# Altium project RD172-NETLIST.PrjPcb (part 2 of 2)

## Sheet 7.SchDoc
size 420 x 297 mm
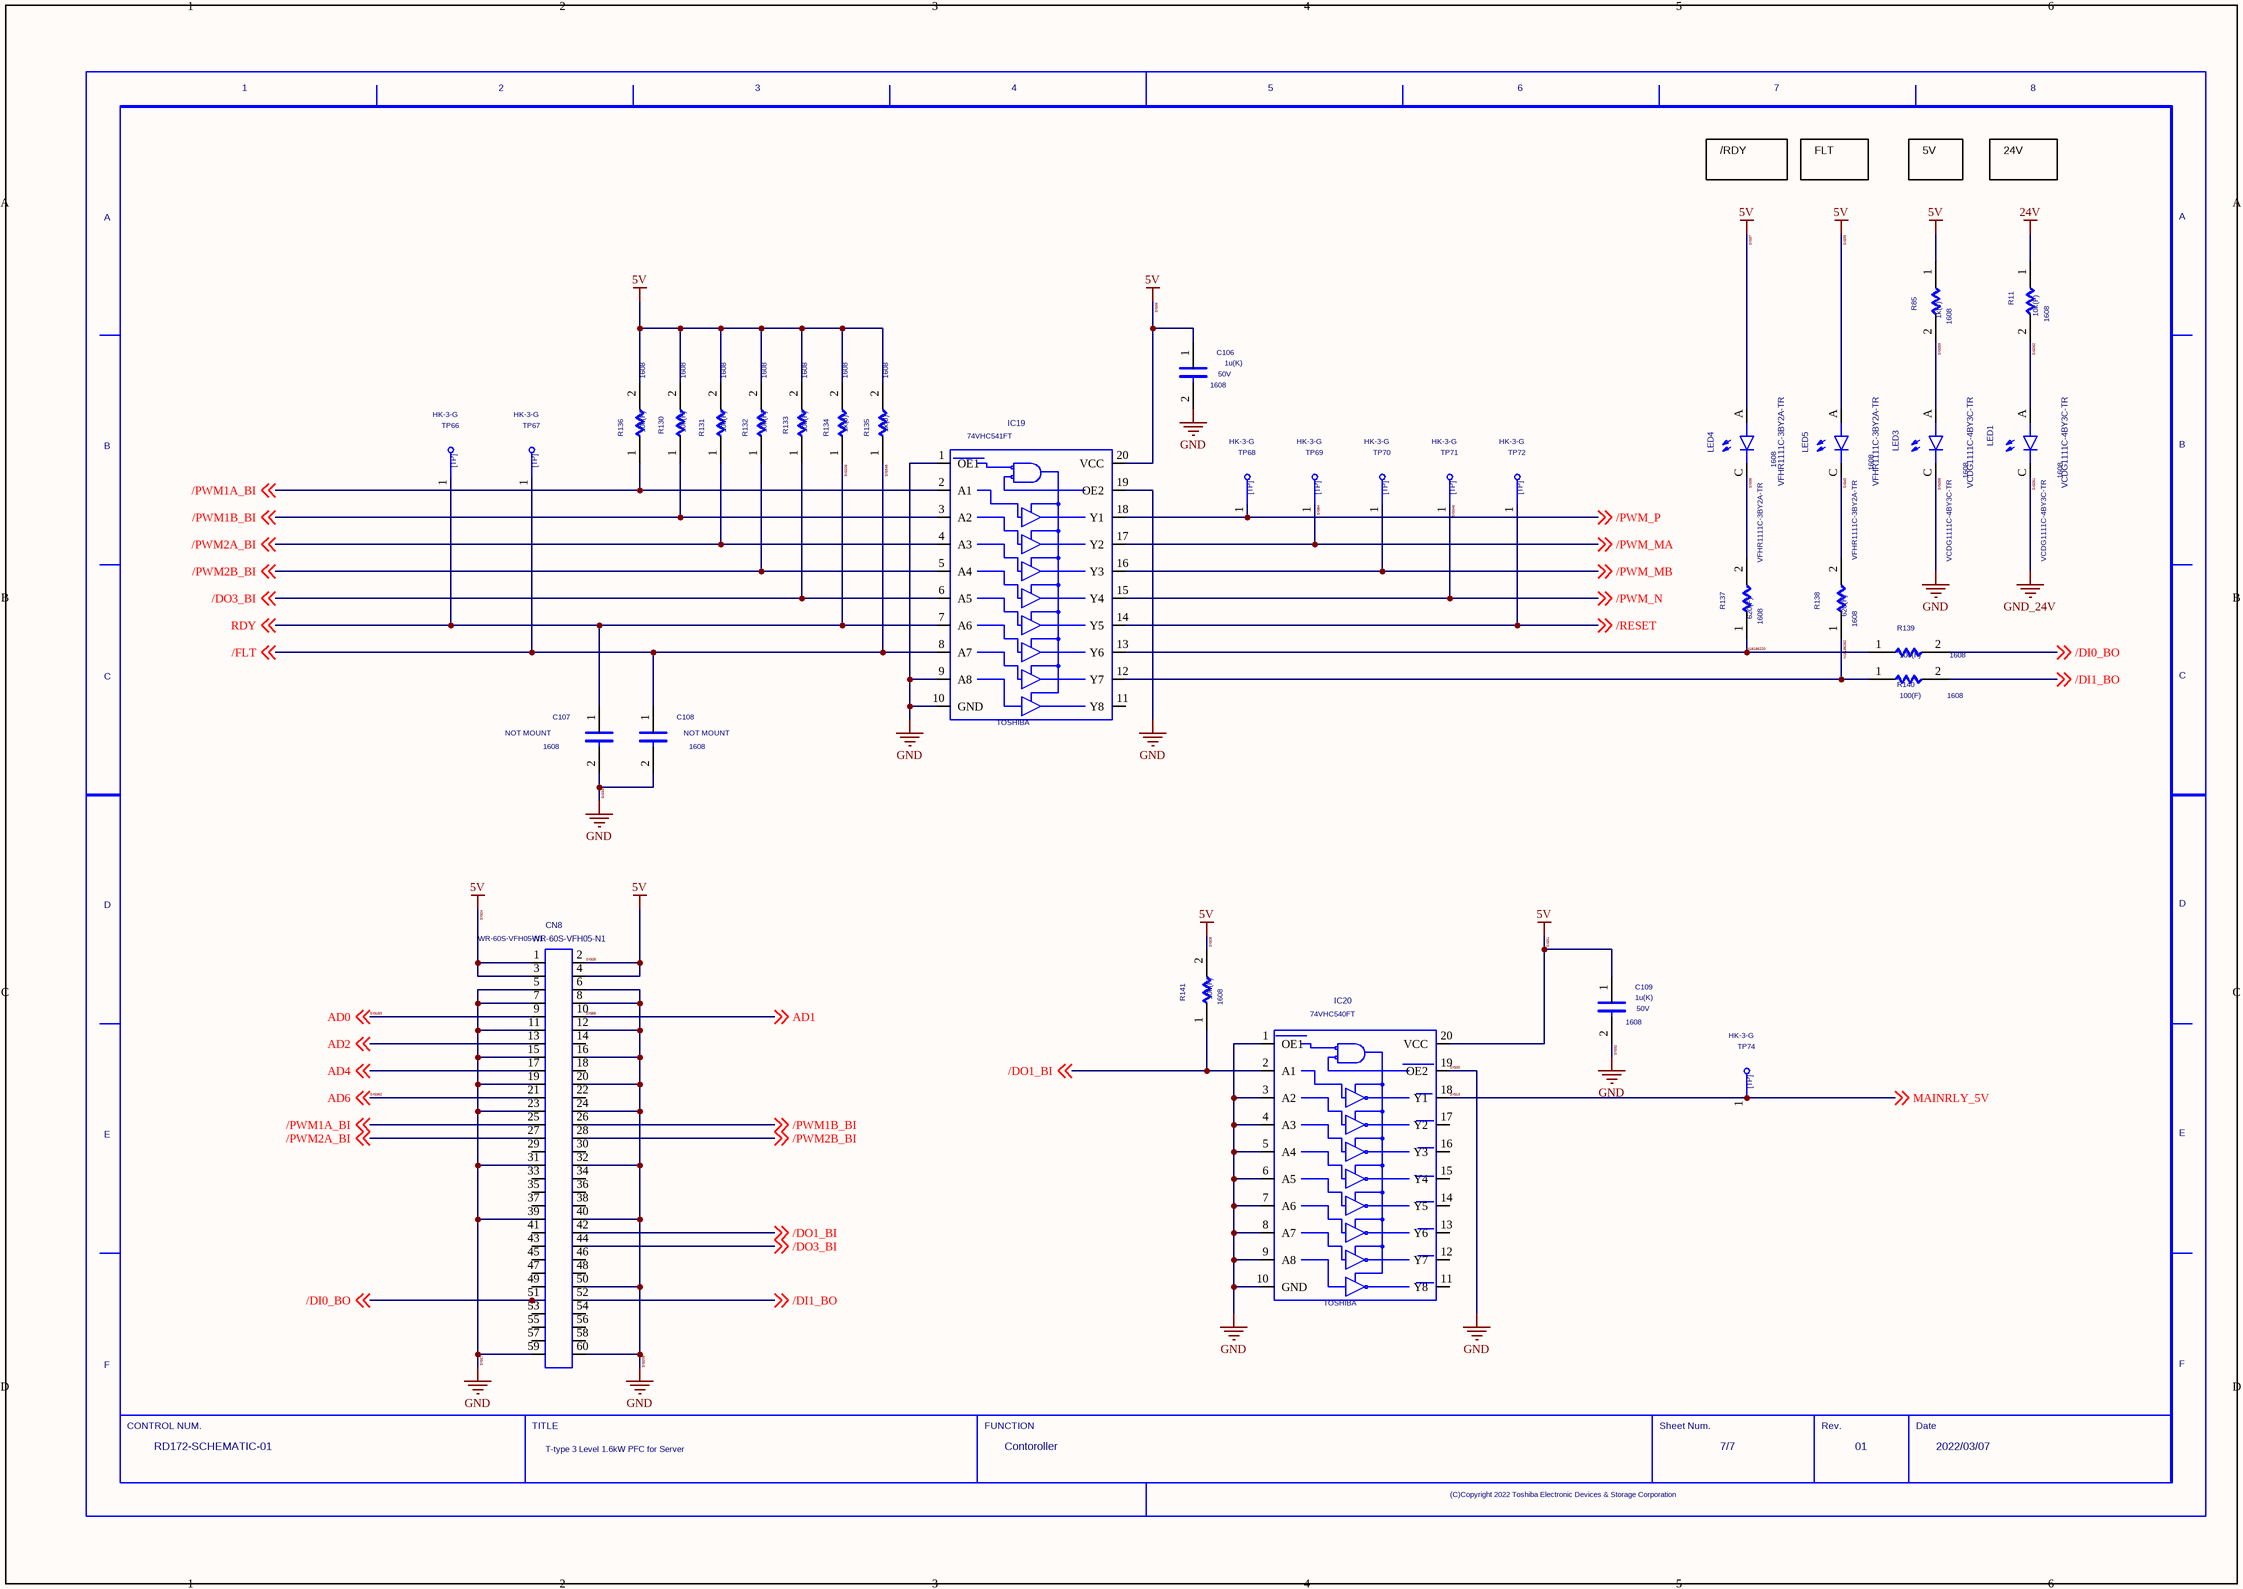
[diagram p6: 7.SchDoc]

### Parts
(Parts that share a designator on the sheet are numbered #1, #2 ... from top to bottom, then left to right.)
C106  SIZECODESMD: 1608  VAL2: 50V  VAL1: 1u(K)  (hidden comment: C)
C107  SIZECODESMD: 1608  NOTMOUNT: NOT MOUNT  (hidden comment: C)
C108  SIZECODESMD: 1608  NOTMOUNT: NOT MOUNT  (hidden comment: C)
C109  SIZECODESMD: 1608  VAL2: 50V  VAL1: 1u(K)  (hidden comment: C)
CN8  WR-60S-VFH05-N1
IC19  USERCOMPTEXT3: TOSHIBA  (hidden comment: 74VHC541FT)
IC20  USERCOMPTEXT3: TOSHIBA  (hidden comment: 74VHC540FT)
LED1  VCDG1111C-4BY3C-TR  SIZECODESMD: 1608
LED3  VCDG1111C-4BY3C-TR  SIZECODESMD: 1608
LED4  VFHR1111C-3BY2A-TR  SIZECODESMD: 1608
LED5  VFHR1111C-3BY2A-TR  SIZECODESMD: 1608
R11  SIZECODESMD: 1608  VAL1: 10k(F)  (hidden comment: R)
R85  SIZECODESMD: 1608  VAL1: 1k(J)  (hidden comment: R)
R130  SIZECODESMD: 1608  VAL1: 10k(F)  (hidden comment: R)
R131  SIZECODESMD: 1608  VAL1: 10k(F)  (hidden comment: R)
R132  SIZECODESMD: 1608  VAL1: 10k(F)  (hidden comment: R)
R133  SIZECODESMD: 1608  VAL1: 10k(F)  (hidden comment: R)
R134  SIZECODESMD: 1608  VAL1: 1k(J)  (hidden comment: R)
R135  SIZECODESMD: 1608  VAL1: 1k(J)  (hidden comment: R)
R136  SIZECODESMD: 1608  VAL1: 10k(F)  (hidden comment: R)
R137  SIZECODESMD: 1608  VAL1: 620(F)  (hidden comment: R)
R138  SIZECODESMD: 1608  VAL1: 620(F)  (hidden comment: R)
R139  SIZECODESMD: 1608  VAL1: 100(F)  (hidden comment: R)
R140  SIZECODESMD: 1608  VAL1: 100(F)  (hidden comment: R)
R141  SIZECODESMD: 1608  VAL1: 10k(F)  (hidden comment: R)
TP66  VAL3: HK-3-G  (hidden comment: TP)
TP67  VAL3: HK-3-G  (hidden comment: TP)
TP68  VAL3: HK-3-G  (hidden comment: TP)
TP69  VAL3: HK-3-G  (hidden comment: TP)
TP70  VAL3: HK-3-G  (hidden comment: TP)
TP71  VAL3: HK-3-G  (hidden comment: TP)
TP72  VAL3: HK-3-G  (hidden comment: TP)
TP74  VAL3: HK-3-G  (hidden comment: TP)
U?#7  DATE: 2022/03/07  REVISION: 01  SHEETNUMBER: 7/7  FUNCTION: Contoroller  TITLE: T-type 3 Level 1.6kW PFC for Server  DRAWINGNUMBER: RD172-SCHEMATIC-01  (hidden comment: WAKU_DEF100)

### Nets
5V: C106.1 C109.1 CN8.1 CN8.2 CN8.3 CN8.4 IC19.20(VCC) IC20.20(VCC) LED4.A LED5.A R85.1 R130.2 R131.2 R132.2 R133.2 R134.2 R135.2 R136.2 R141.2  [also labelled SIG24, SIG25, SIG28, SIG31, SIG36, SIG37, SIG39]  [project net SIG177]
24V: R11.1  [project net SIG18]
GND: C106.2 C107.2 C108.2 C109.2 CN8.5 CN8.6 CN8.7 CN8.8 CN8.11 CN8.12 CN8.15 CN8.16 CN8.19 CN8.20 CN8.23 CN8.24 CN8.31 CN8.32 CN8.39 CN8.40 CN8.50 CN8.59 CN8.60 IC19.1(OE1) IC19.9(A8) IC19.10(GND) IC19.19(OE2) IC20.1(OE1) IC20.3(A2) IC20.4(A3) IC20.5(A4) IC20.6(A5) IC20.7(A6) IC20.8(A7) IC20.9(A8) IC20.10(GND) IC20.19(OE2) LED3.C  [also labelled SIG208, SIG258, SIG27, SIG30, SIG32, SIG34]  [project net SIG157]
GND_24V: LED1.C  [also labelled SIG261]  [project net SIG17]
/DI0_BO: CN8.51 R139.2 ; off-sheet /DI0_BO
/DI1_BO: CN8.52 R140.2 ; off-sheet /DI1_BO
/DO1_BI: CN8.42 IC20.2(A1) R141.1 ; off-sheet /DO1_BI
/DO3_BI: CN8.44 IC19.6(A5) R133.1 ; off-sheet /DO3_BI
/PWM1A_BI: CN8.25 IC19.2(A1) R136.1 ; off-sheet /PWM1A_BI
/PWM1B_BI: CN8.26 IC19.3(A2) R130.1 ; off-sheet /PWM1B_BI
/PWM2A_BI: CN8.27 IC19.4(A3) R131.1 ; off-sheet /PWM2A_BI
/PWM2B_BI: CN8.28 IC19.5(A4) R132.1 ; off-sheet /PWM2B_BI
/PWM_MB: IC19.16(Y3) TP70.1 ; off-sheet /PWM_MB
/PWM_P: IC19.18(Y1) TP68.1 ; off-sheet /PWM_P
/RESET: IC19.14(Y5) TP72.1 ; off-sheet /RESET
AD2: CN8.13 ; off-sheet AD2
AD4: CN8.17 ; off-sheet AD4
N18186220: IC19.13(Y6) R137.1 R139.1
N18186262: IC19.12(Y7) R138.1 R140.1
SIG13: IC20.18(Y1) TP74.1 ; off-sheet MAINRLY_5V  [also labelled MAINRLY_5V]
SIG38: LED4.C R137.2
SIG40: LED5.C R138.2
SIG55: CN8.10 ; off-sheet AD1  [also labelled AD1]
SIG84: IC19.17(Y2) TP69.1 ; off-sheet /PWM_MA  [also labelled /PWM_MA]
SIG153: CN8.9 ; off-sheet AD0  [also labelled AD0]
SIG205: C107.1 IC19.7(A6) R134.1 TP66.1 ; off-sheet RDY  [also labelled RDY]
SIG259: LED3.A R85.2
SIG262: LED1.A R11.2
SIG345: C108.1 IC19.8(A7) R135.1 TP67.1 ; off-sheet /FLT  [also labelled /FLT]
SIG346: IC19.15(Y4) TP71.1 ; off-sheet /PWM_N  [also labelled /PWM_N]
SIG362: CN8.21 ; off-sheet AD6  [also labelled AD6]

Not connected (* = marked no-connect by the designer): CN8 14 18 22 29 30 33 34 35 36 37 38 41 43 45 46 47 48 49 53 54 55 56 57 58; IC19 11(Y8); IC20 11(Y8) 12(Y7) 13(Y6) 14(Y5) 15(Y4) 16(Y3) 17(Y2)

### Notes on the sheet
- /RDY
- FLT
- 5V
- 24V

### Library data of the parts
C106 C109 = C: OriginalSymbolOrigin: (2540,7620); COMP: -C-UMK107AB7105KA-T
C107 C108 = C: OriginalSymbolOrigin: (2540,7620); COMP: -C-NC_C1608
CN8 = WR_60S_VFH05_N1: Terminal, 200V, 0.3A; MANUFACTURER: JAE; COMP: -CN-WR-60S-VFH05-N1; NOTE: 60pin; TIME: 16:53:54; UPDATEUSER: t5459927; UPDATETIME: 14:46:38; SAVECOUNT: 2; SAVEAREA0: -56595,-80318,58967,4405; OriginalSymbolOrigin: (0,0)
IC19 = 74VHC541FT_0: Buffer; COMP: -IC-74VHC541FT; TIME: 16:53:58; UPDATEUSER: t5459927; UPDATETIME: 14:50:23; SAVECOUNT: 2; SAVEAREA0: -22847,-24597,51708,30063; OriginalSymbolOrigin: (0,0)
IC20 = 74VHC540FT: Buffer; COMP: -IC-74VHC540FT; TIME: 16:53:55; UPDATEUSER: t5459927; UPDATETIME: 14:48:47; SAVECOUNT: 2; SAVEAREA0: -22628,-27657,51926,27001; OriginalSymbolOrigin: (0,0)
LED1 LED3 = VCDG1111C_4BY3C_TR: LED; MANUFACTURER: STANLEY; COMP: -LED-VCDG1111C-4BY3C-TR_AC; NOTE: Green; TIME: 16:53:54; UPDATEUSER: t5459927; SAVECOUNT: 1; OriginalSymbolOrigin: (0,-2540); INSTANCENAME: INS18172566
LED4 LED5 = VFHR1111C_3BY2A_TR: LED; MANUFACTURER: STANLEY; COMP: -LED-VFHR1111C-3BY2A-TR_AC; NOTE: Red; TIME: 16:53:54; UPDATEUSER: t5459927; SAVECOUNT: 1; OriginalSymbolOrigin: (0,-2540); INSTANCENAME: INS18256251
R11 R130-R133 R136 R141 = R: OriginalSymbolOrigin: (5080,5080); VAL2: 100mW; COMP: -R-ERJ3EKF1002V
R85 R134 R135 = R: OriginalSymbolOrigin: (5080,5080); VAL2: 125mW; COMP: -R-RK73B1JTTD102J
R137 R138 = R: OriginalSymbolOrigin: (5080,5080); COMP: -R-ERJ3EKF6200V; VAL2: 100mW
R139 R140 = R: OriginalSymbolOrigin: (5080,5080); COMP: -R-ERJ3EKF1000V; VAL2: 100mW
TP66-TP72 TP74 = TP: TIME: 16:12:21; UPDATEUSER: fukuda-y; UPDATETIME: 16:18:11; SAVECOUNT: 2; SAVEAREA0: -242,-92,12810,7836; OriginalSymbolOrigin: (0,7620); COMP: -TP-HK-3-G
U?#7 = WAKU_DEF100: PLOTTIME: HH:MM; SAVEAREA0: 22200,72372,612276,319236; TIME: 14:30:25; UPDATEUSER: t5459927; UPDATETIME: 09:34:25; SAVECOUNT: 7; OriginalSymbolOrigin: (10160,284480)

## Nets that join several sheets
+15V_N: 2 (6 pins), 6 (C38.1 IC6.1 R43.2 TP27.1)
GND_N: 2 (26 pins), 6 (7 pins)
SIG17: 1 (C4.2 Q2.S R17.1), 6 (14 pins), 7 (LED1.C)
SIG18: 1 (5 pins), 6 (14 pins), 7 (R11.1)
SIG103: 5 (C85.1 D23.C IC15.1), 6 (6 pins)
SIG157: 1 (5 pins), 2 (12 pins), 3 (6 pins), 4 (7 pins), 5 (15 pins), 6 (11 pins), 7 (38 pins)
SIG177: 1 (C71.1 CT1.Vcc), 2 (16 pins), 3 (8 pins), 4 (C72.1 D22.C IC13.4 R82.2), 5 (11 pins), 6 (9 pins), 7 (19 pins)
SIG213: 3 (25 pins), 6 (7 pins)
SIG285: 3 (6 pins), 6 (C53.1 IC9.1 R57.2 TP33.1)
SIG299: 5 (C85.2 IC15.4 R97.2), 6 (6 pins)
SIG306: 2 (6 pins), 6 (C21.1 IC2.1 R22.2 TP17.1)
SIG307: 2 (26 pins), 6 (7 pins)
SIG355: 5 (6 pins), 6 (6 pins)
SIG360: 5 (6 pins), 6 (6 pins)
/PWM_MB: 3 (IC12.11 R72.1), 7 (IC19.16 TP70.1)
/PWM_P: 2 (IC1.11 IC3.11 R19.1 R28.1), 7 (IC19.18 TP68.1)
/RESET: 2 (IC1.14 IC3.14 IC5.14 IC7.14), 3 (IC10.14 IC12.14), 7 (IC19.14 TP72.1)
AC_L2: 1 (6 pins), 2 (D7.A D12.C)
AC_L_IN: 1 (6 pins), 5 (R88.1), 6 (PS1.2 TP10.1)
AC_N2: 1 (CT1.8 CT1.9 CT1.10), 2 (L3.1), 5 (C87.2 L5.2 R94.1 R100.1)
AC_N_IN: 1 (8 pins), 6 (PS1.1 TP8.1)
AD2: 4 (C70.2 IC13.14 R79.2 TP46.1), 7 (CN8.13)
AD4: 5 (C94.2 IC17.1 R108.2 TP59.1), 7 (CN8.17)
SIG13: 1 (R14.1), 7 (IC20.18 TP74.1)
SIG55: 4 (IC13.8 IC13.9 TP47.1), 7 (CN8.10)
SIG84: 3 (IC10.11 R62.1), 7 (IC19.17 TP69.1)
SIG153: 5 (C88.2 IC17.14 R96.2 TP58.1), 7 (CN8.9)
SIG205: 2 (IC1.12 IC3.12 IC5.12 IC7.12), 3 (IC10.12 IC12.12), 7 (C107.1 IC19.7 R134.1 TP66.1)
SIG209: 2 (6 pins), 3 (8 pins), 5 (8 pins)
SIG221: 4 (C73.2 R81.2), 5 (C89.1 IC17.8 IC17.9 R99.1)
SIG345: 2 (IC1.13 IC3.13 IC5.13 IC7.13), 3 (IC10.13 IC12.13), 7 (C108.1 IC19.8 R135.1 TP67.1)
SIG346: 2 (IC5.11 IC7.11 R38.1 R47.1), 7 (IC19.15 TP71.1)
SIG362: 5 (C97.2 IC17.7 R124.2 TP62.1), 7 (CN8.21)
Vdc_M: 2 (9 pins), 3 (D28.C Q7.D)
Vdc_M_dct: 3 (14 pins), 5 (R102.1)
Vdc_P: 2 (D6.C D7.C D26.C Q3.D), 3 (8 pins), 5 (R117.1)
Vo_Isen: 1 (CT1.Vo), 4 (IC13.5 TP44.1)
Vref_Isen: 1 (CT1.Vref), 4 (IC13.3 TP45.1)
